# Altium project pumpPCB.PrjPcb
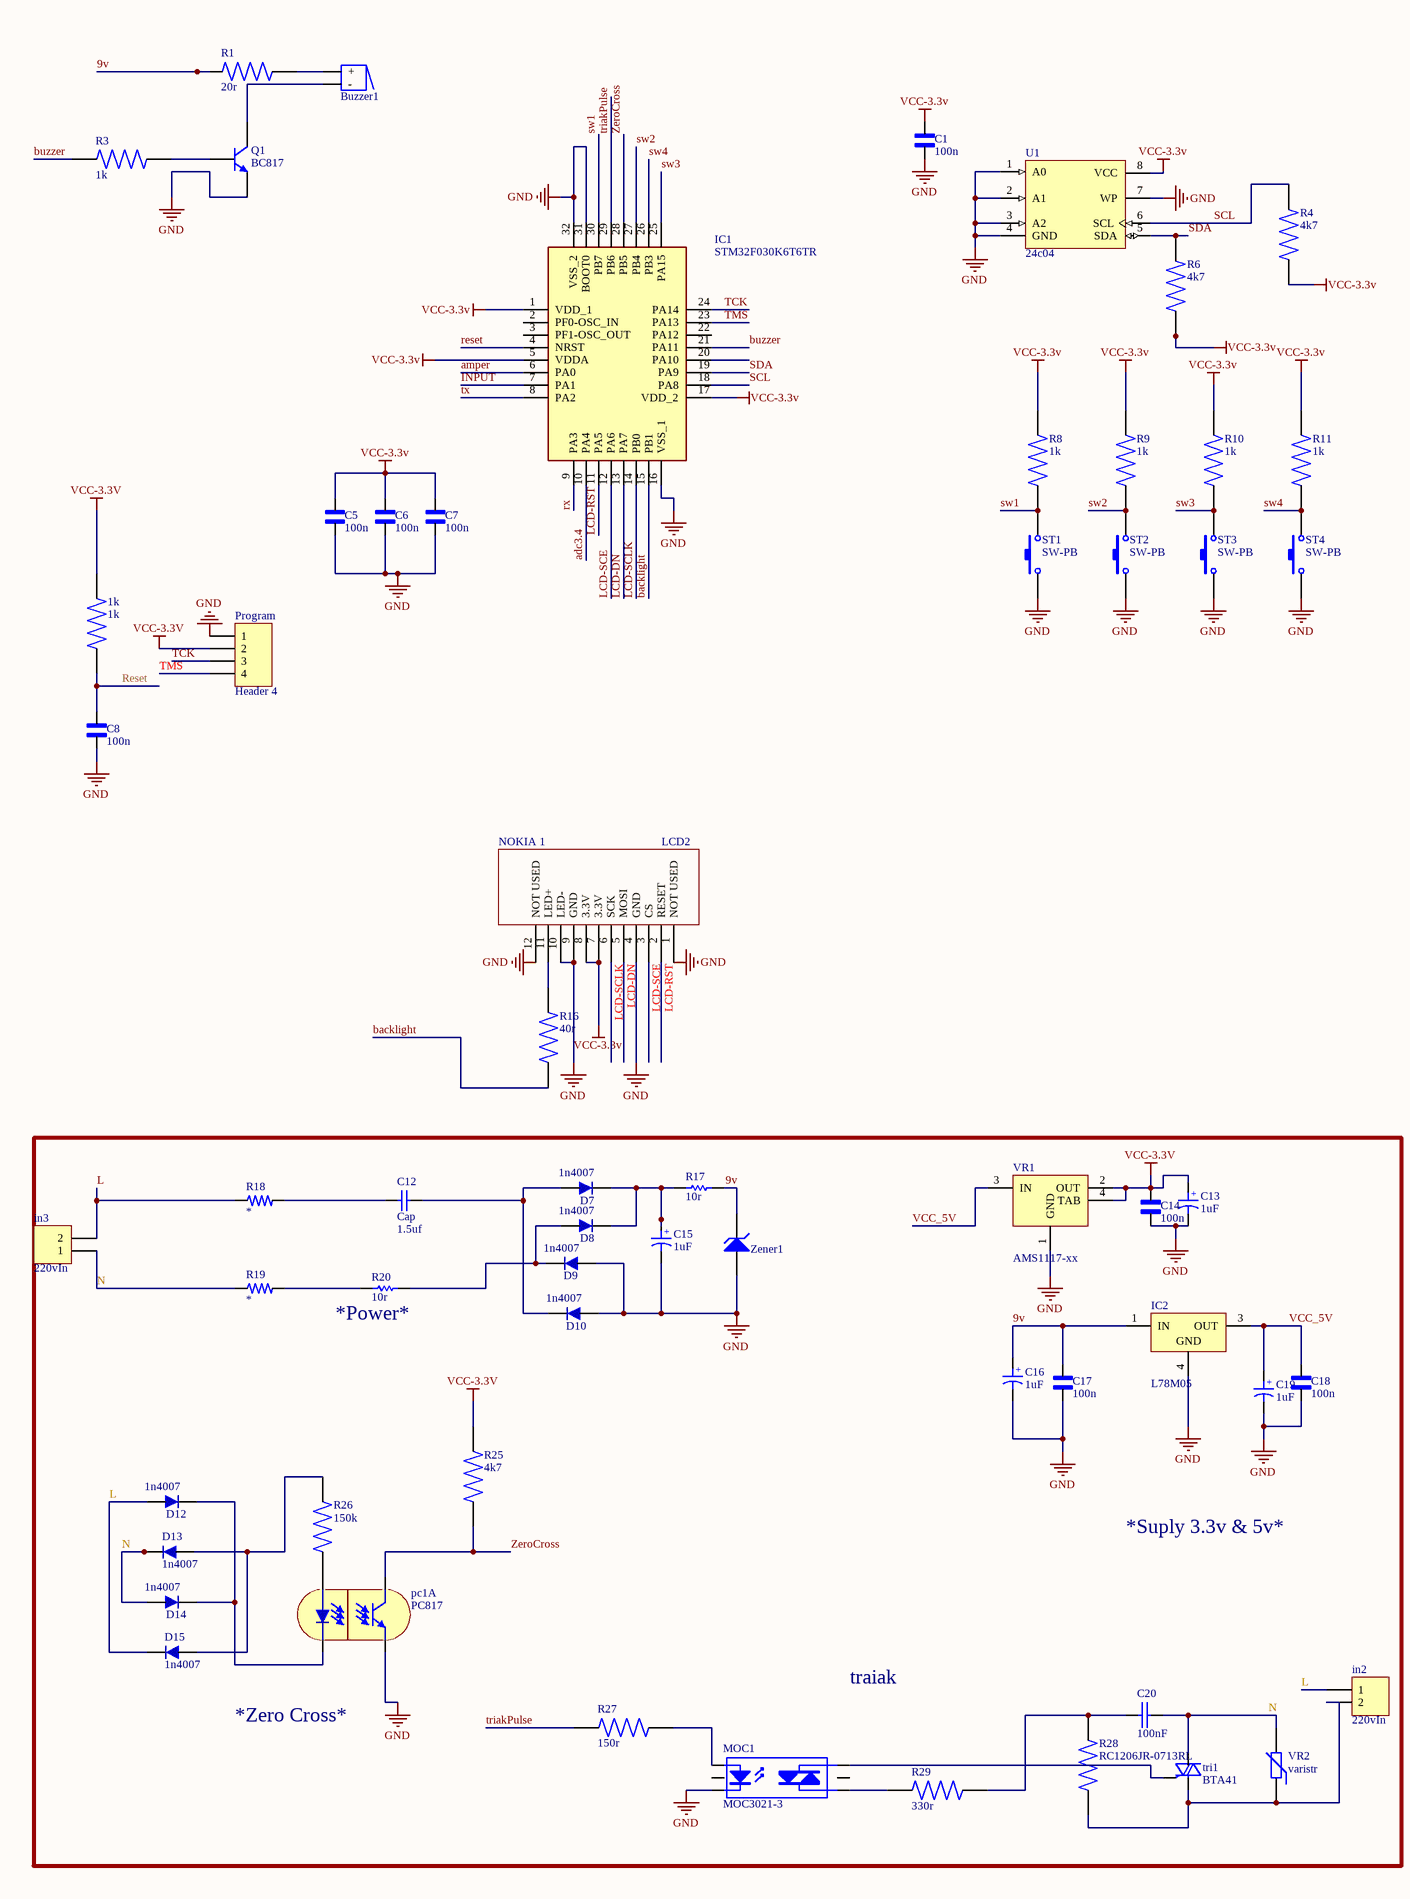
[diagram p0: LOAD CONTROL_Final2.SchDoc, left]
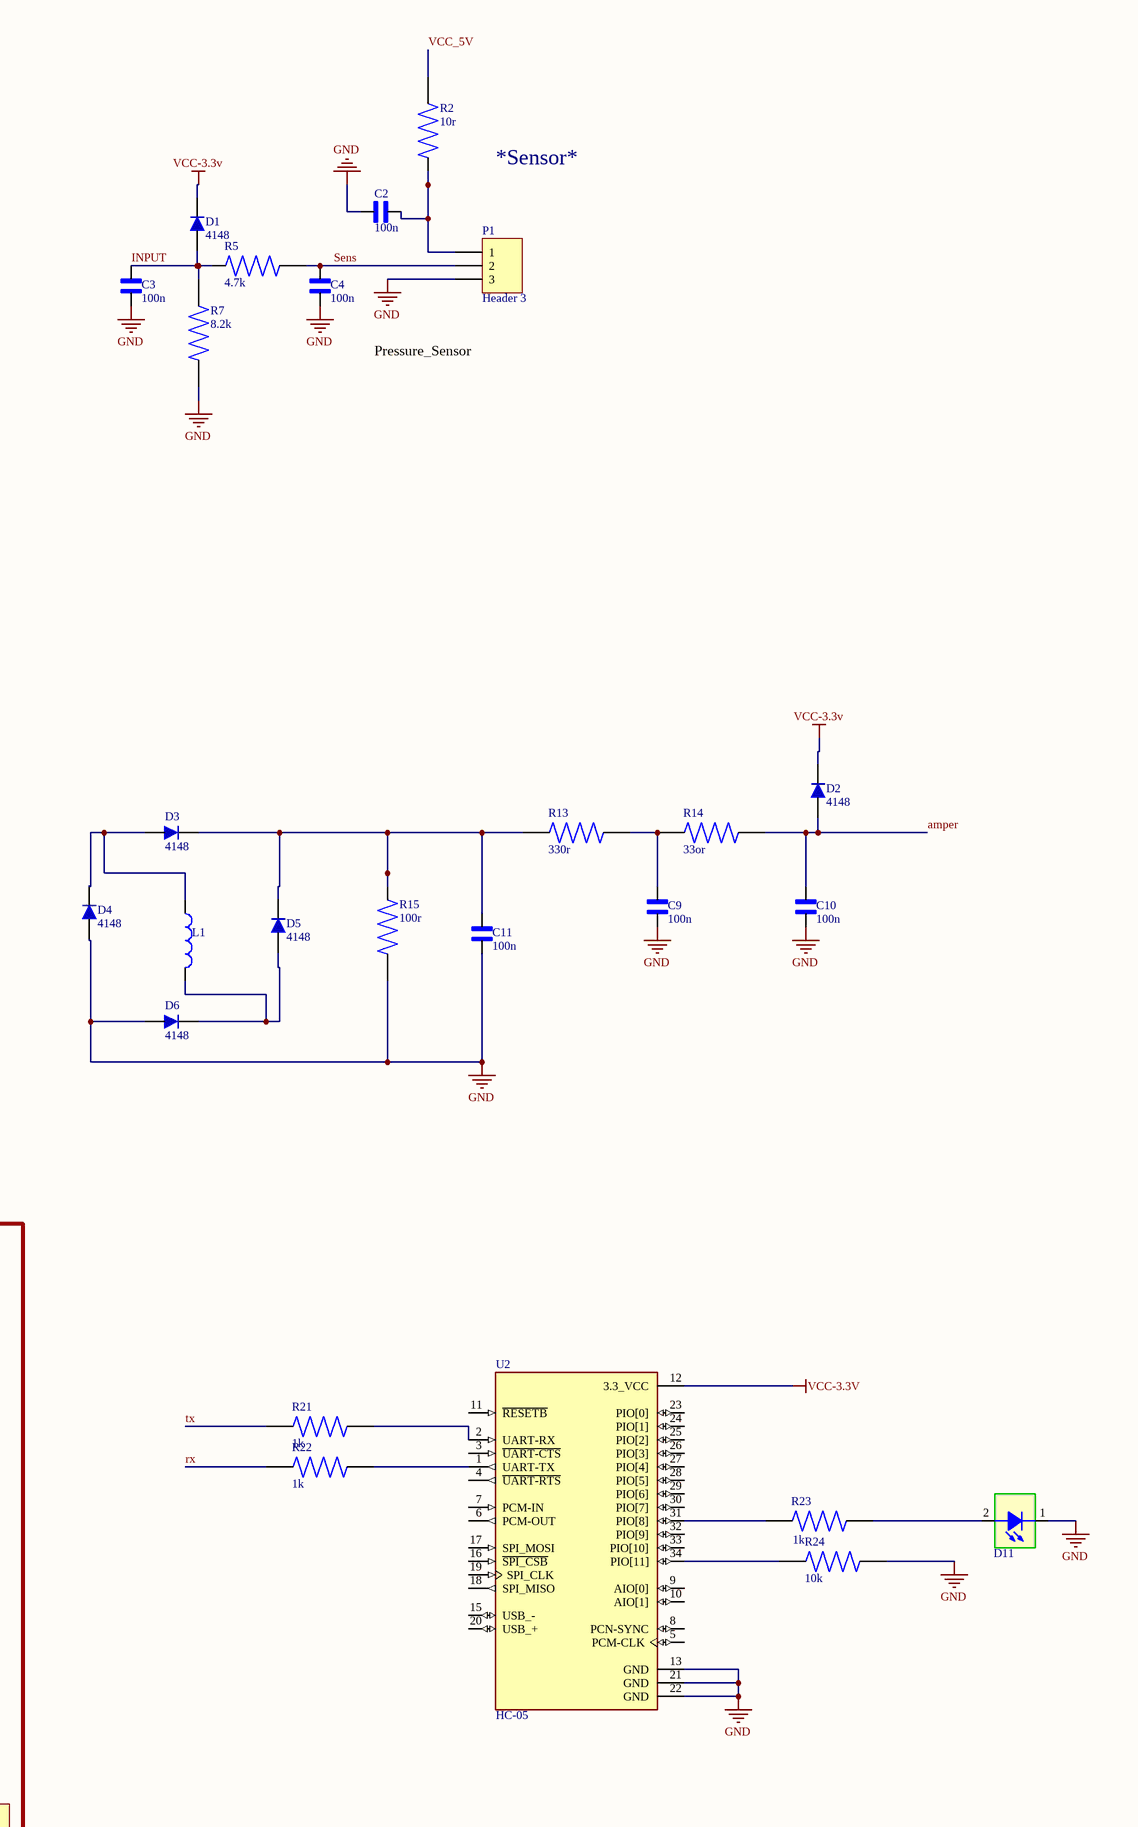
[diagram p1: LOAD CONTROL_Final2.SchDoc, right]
1 sheet, 86 parts. Net scope: global (net labels, ports and power ports of the same name join across sheets).
Board file: PumpControl.PcbDoc

## Sheet LOAD CONTROL_Final2.SchDoc
size A2

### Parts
1k  1k  [RESC3116X65N]
Buzzer1  Buzzer  [BUZZER]  (value not drawn)
C1  100n  [CAPC3216X88N]
C2  100n  [CAPC3216X88N]
C3  100n  [CAPC3216X88N]
C4  100n  [CAPC3216X88N]
C5  100n  [CAPC3216X88N]
C6  100n  [CAPC3216X88N]
C7  100n  [CAPC3216X88N]
C8  100n  [CAPC3216X88N]
C9  100n  [CAPC3216X88N]
C10  100n  [CAPC3216X88N]
C11  100n  [CAPC3216X88N]
C12  Cap  value 1.5uf  [RAD-0.3]
C13  1uF  [Cap electrolitic radial 5x11-2]
C14  100n  [CAPC3216X88N]
C15  1uF  [Cap electrolitic radial 5x11-2]
C16  1uF  [Cap electrolitic radial 5x11-2]
C17  100n  [CAPC3216X88N]
C18  100n  [CAPC3216X88N]
C19  1uF  [Cap electrolitic radial 5x11-2]
C20  100nF  [Cap 10nF]
D1  4148  [SOD80, LL-34]
D2  4148  [SOD80, LL-34]
D3  4148  [SOD80, LL-34]
D4  4148  [SOD80, LL-34]
D5  4148  [SOD80, LL-34]
D6  4148  [SOD80, LL-34]
D7  1n4007  [DIOM4629X24N]
D8  1n4007  [DIOM4629X24N]
D9  1n4007  [DIOM4629X24N]
D10  1n4007  [DIOM4629X24N]
D11  LED  [LED 1206]  (value not drawn)
D12  1n4007  [DIOM4629X24N]
D13  1n4007  [DIOM4629X24N]
D14  1n4007  [DIOM4629X24N]
D15  1n4007  [DIOM4629X24N]
IC1  STM32F030K6T6TR  [QFP80P900X900X160-32N]
IC2  L78M05  [TO-252]
in2  220vIn  [HDR1X2]
in3  220vIn  [HDR1X2]
L1  0  [ZMC]  (value not drawn)
MOC1  MOC3021-3  [DIP-6]
NOKIA_1  LCD2  [LCD NOKIA 1202]
P1  Header 3  [3PIN]
pc1  PC817  [SMT Gullwing Lead-Form]  (parts A,B of 2)
Program  Header 4  [HDR1X4]
Q1  BC817  [SOT23_N]
R1  20r  [RESC3116X65N]
R2  10r  [RESC3116X65N]
R3  1k  [RESC3116X65N]
R4  4k7  [RESC3116X65N]
R5  4.7k  [RESC3116X65N]
R6  4k7  [RESC3116X65N]
R7  8.2k  [RESC3116X65N]
R8  1k  [RESC3116X65N]
R9  1k  [RESC3116X65N]
R10  1k  [RESC3116X65N]
R11  1k  [RESC3116X65N]
R13  330r  [RESC3116X65N]
R14  33or  [RESC3116X65N]
R15  100r  [RESC3116X65N]
R16  40r  [RESC3116X65N]
R17  10r  [RES-(1/2)-Stand]
R18  100uh  [RESAD640W45L370D200]  (value not drawn)
R19  100uh  [RESAD640W45L370D200]  (value not drawn)
R20  10r  [RES-(1/2)-Stand]
R21  1k  [RESC3116X65N]
R22  1k  [RESC3116X65N]
R23  1k  [RESC3116X65N]
R24  10k  [RESC3116X65N]
R25  4k7  [RESC3116X65N]
R26  150k  [RESC3116X65N]
R27  150r  [RESC3116X65N]
R28  RC1206JR-0713RL  [RESC3116X65N]
R29  330r  [RESC3116X65N]
ST1  SW-PB  [PUSH BOTTOM 6*6]
ST2  SW-PB  [PUSH BOTTOM 6*6]
ST3  SW-PB  [PUSH BOTTOM 6*6]
ST4  SW-PB  [PUSH BOTTOM 6*6]
tri1  BTA41  [TO552P1530X450X2110-3B]
U1  24c04  [SO8_L]
U2  HC-05  [XCVR_HC-05]
VR1  AMS1117-xx  [SOT-223]
VR2  varistr  [14D XXX]
Zener1  9v  [Diode 1W_Stand]  (value not drawn)

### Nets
GND: C1.1 C2.2 C3.1 C4.1 C5.1 C6.1 C7.1 C8.1 C9.1 C10.1 C11.1 C13.2 C14.1 C15.2 C16.2 C17.1 C18.1 C19.2 D4.1 D6.1 D9.1 D10.1 D11.1 IC1.16(VSS_1) IC1.31(BOOT0) IC1.32(VSS_2) IC2.4(GND) MOC1.2(K) NOKIA_1.1(NOT_USED) NOKIA_1.4(GND) NOKIA_1.9(GND) NOKIA_1.10(LED-) NOKIA_1.12(NOT_USED) P1.3 pc1.3(E) Program.1 Q1.2(E) R7.1 R15.1 R24.1 ST1.1 ST2.1 ST3.1 ST4.1 U1.1(A0) U1.2(A1) U1.3(A2) U1.4(GND) U1.7(WP) U2.13(GND) U2.21(GND) U2.22(GND) VR1.1(GND) Zener1.1(A)
VCC-3.3v: 1k.2 C1.2 C5.2 C6.2 C7.2 C13.1 C14.2 D1.2 D2.2 IC1.1(VDD_1) IC1.5(VDDA) IC1.17(VDD_2) NOKIA_1.7(3.3V) NOKIA_1.8(3.3V) Program.2 R4.1 R6.1 R8.2 R9.2 R10.2 R11.2 R25.2 U1.8(VCC) U2.12(3.3_VCC) VR1.2(OUT) VR1.4(TAB)
9v: C16.1 C17.2 IC2.1(IN) R1.1 R17.2 Zener1.2(K)
adc3.4: IC1.10(PA4)
amper: C10.2 D2.1 IC1.6(PA0) R14.1
backlight: IC1.15(PB1) R16.1
buzzer: IC1.21(PA11) R3.1
INPUT: C3.2 D1.1 IC1.7(PA1) R5.2 R7.2
L: D12.1 D15.2 in2.1 in3.2 R18.1
LCD-DN: IC1.13(PA7) NOKIA_1.5(MOSI)
LCD-RST: IC1.11(PA5) NOKIA_1.2(RESET)
LCD-SCE: IC1.12(PA6) NOKIA_1.3(CS)
LCD-SCLK: IC1.14(PB0) NOKIA_1.6(SCK)
N: C20.2(-) D13.2 D14.1 in3.1 R19.1 tri1.2(A2) VR2.2
Reset: 1k.1 C8.2 IC1.4(NRST)
rx: IC1.9(PA3) R22.2
SCL: IC1.18(PA8) R4.2 U1.6(SCL)
SDA: IC1.19(PA9) R6.2 U1.5(SDA)
Sens: C4.2 P1.2 R5.1
sw1: IC1.30(PB7) R8.1 ST1.2
sw2: IC1.27(PB4) R9.1 ST2.2
sw3: IC1.25(PA15) R10.1 ST3.2
sw4: IC1.26(PB3) R11.1 ST4.2
TCK: IC1.24(PA14) Program.3
TMS: IC1.23(PA13) Program.4
triakPulse: IC1.29(PB6) R27.2
tx: IC1.8(PA2) R21.2
VCC_5V: C18.2 C19.1 IC2.3(OUT) R2.1 VR1.3(IN)
ZeroCross: IC1.28(PB5) pc1.4(C) R25.1
NetBuzzer1_1: Buzzer1.1(+) R1.2
NetBuzzer1_2: Buzzer1.2(-) Q1.3(C)
NetC2_1: C2.1 P1.1 R2.2
NetC9_2: C9.2 R13.1 R14.2
NetC11_2: C11.2 D3.2 D5.2 R13.2 R15.2
NetC12_1: C12.1 R18.2
NetC12_2: C12.2 D7.1 D10.2
NetC15_1: C15.1 D7.2 D8.2 R17.1
NetC20_1: C20.1(+) R28.1 R29.1
NetD3_1: D3.1 D4.2 L1.1
NetD5_1: D5.1 D6.2 L1.2
NetD8_1: D8.1 D9.2 R20.2
NetD11_2: D11.2 R23.1
NetD12_2: D12.2 D14.2 pc1.2(K)
NetD13_1: D13.1 D15.1 R26.2
Netin2_2: in2.2 R28.2 tri1.1(A1) VR2.1
NetMOC1_1: MOC1.1(A) R27.1
NetMOC1_4: MOC1.4(A/K) tri1.3(G)
NetMOC1_6: MOC1.6(A/K) R29.2
NetNOKIA_1_11: NOKIA_1.11(LED+) R16.2
Netpc1_1: pc1.1(A) R26.1
NetQ1_1: Q1.1(B) R3.2
NetR19_2: R19.2 R20.1
NetR21_1: R21.1 U2.2(UART-RX)
NetR22_1: R22.1 U2.1(UART-TX)
NetR23_2: R23.2 U2.31(PIO[8])
NetR24_2: R24.2 U2.34(PIO[11])

Not connected (* = marked no-connect by the designer): IC1 2(PF0-OSC_IN) 3(PF1-OSC_OUT) 20(PA10) 22(PA12); MOC1 3(NC) 5(NC); U2 3(~{UART-CTS}) 4(~{UART-RTS}) 5(PCM-CLK) 6(PCM-OUT) 7(PCM-IN) 8(PCN-SYNC) 9(AIO[0]) 10(AIO[1]) 11(~{RESETB}) 15(USB_-) 16(~{SPI_CSB}) 17(SPI_MOSI) 18(SPI_MISO) 19(SPI_CLK) 20(USB_+) 23(PIO[0]) 24(PIO[1]) 25(PIO[2]) 26(PIO[3]) 27(PIO[4]) 28(PIO[5]) 29(PIO[6]) 30(PIO[7]) 32(PIO[9]) 33(PIO[10])

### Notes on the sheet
- *Sensor*
- Pressure_Sensor
- (near R20) *Power*
- *Suply 3.3v & 5v*
- traiak
- *Zero Cross*

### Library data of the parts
1k R1-R11 R13-R16 R21-R29 = RC1206JR-0713RL: 13 Ohms Â±5% 0.25W, 1/4W Chip Resistor 1206 (3216 Metric) Moisture Resistant Thick Film; MF: Yageo
Buzzer1 = Buzzer: Designer: Seyed Mohsen Ghasemain
C1-C11 C14 C17 C18 = C1206C120J5GACTU: 1206 C 12pF Ceramic Multilayer Capacitor, 50 VDC, +125degC, C0G Dielec, +/-5% ¦ KEMET C1206C120J5GACTU
C12 = Cap: Capacitor
C13 C15 C16 C19 = Cap ELECTROLITIC TOTAL SIZE: Cap electrolitic radial; Designer: Abbas Basereh
C20 = Cap-Bipolar: Bipolar Capacitor; Voltage: 100V; Designer: Saeid Jorablo; Organazation: ControTec
D1-D6 = 1N4148UR-1: DIODE GEN PURP 75V 200MA DO213AA
D7-D10 D12-D15 = 1n4007 SMD M7: Standard Rectifiers; Part. No: M7; Manufacturer: DC COMPONENTS; Designer: Abbas Basereh
D11 = LED SMD 1206: SMD 1206 LED
IC1 = STM32F030K6T6TR: Integrated Circuit; Manufacturer_Name: STMicroelectronics
IC2 = L78M05: Precision 500mA Regulator
in2 in3 = Header 2: Header, 2-Pin
L1 = Inductor: Code_IEC: 1005; Value: 300uH
MOC1 = MOC3021-3: Opto-Triac; Designer: Seyed Mohsen Ghasemian; E-mail: picpars@gmail.com
NOKIA_1 = NOKIA 1202
P1 = Header 3: Header, 3-Pin
pc1 = PC817XI: DIP 4pin General Purpose  Photocoupler
Program = Header 4: Header, 4-Pin
Q1 = BC817: 45 V, 500 mA NPN general-purpose transistors
R17 R20 = RES DIP PACKAGE: TOTAL DIP RESISTOR PACK; Designer: Ali Hafizi
R18 R19 = LR0204F13K3: 13.3 kOhms Â±1% 0.25W, 1/4W Through Hole Resistor Axial - Metal Film; MF: TE Connectivity Passive Product
ST1-ST4 = SW-PB: Switch
tri1 = BTA41-600A: Thyristors, Discretes (diodes, transistors, thyristors ...), Semiconductors and Actives, original, triac, thyristors; MF: STMicroelectronics
U1 = AT24C512: EEPROM
U2 = HC-05: Bluetooth to Serial Port Module; MF: ITead Studio
VR1 = AMS1117
VR2 = VARISTOR (VDR): VARISTORS; Manufacturer: china-canada-philipina; Designer: Abbas Basereh; VALUE: xxDxxx; Models: MOV-VDR-COV
Zener1 = Diode Zener: Zener Diode; Designer: Saeid Jorablo; Company: E.P.I.L; Voltage: 3.3 V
